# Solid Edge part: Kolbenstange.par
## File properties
Username: bmolnar
Dokumentum tartalom típus: 0
Author: bmolnar
Last saved by: bmolnar
Revision: 81
Sűrűség: 0,000 kg/m^3
Pontosság: 0,990
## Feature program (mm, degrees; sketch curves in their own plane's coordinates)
base feature "unnamed BaseFeature 1"
sketch for "unnamed Protrusion 1" plane through (34.5, 0, 0) normal (1, 0, 0) x-axis (0, 0, -1)
  circle centre (0, 0) radius 50
extrude "unnamed Protrusion 1" add finite 28 along +normal
sketch for "Furat_1" plane through (-15, 0, 0) normal (-1, 0, 0) x-axis (0, -1, 0)
hole "Furat_1" diameter 10 finite  VBottomAngle = 118 deg
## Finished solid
Body 1: solid body, 13 faces, 19 edges, 8 vertices.
  Faces by surface: plane 7, cylinder 3, cone 2, torus 1
  Edges by curve: circle 9, line 6, ellipse 2, intersection 2
Bounding box of the edges (mm; curved faces can reach further): 77.545 x 100.000 x 100.000, from (-15.0451, -50, -50) to (62.5, 50, 50).
Cylindrical faces by radius (mm): R5 x1, R12.5 x1, R50 x1
Conical faces (half-angle, radius in mm at the cone's reference point): 45 deg R5.553 x1, 59 deg R5 x1
Toroidal faces (ring radius, tube radius in mm): R10.7 r1.8 x1
Planar faces by outward normal: +x 1, +y 1, -x 2, -y 1, oblique 2
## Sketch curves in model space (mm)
circle centre (34.5, 0, 0) radius 50
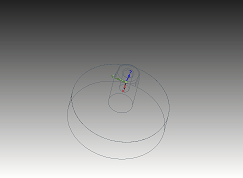
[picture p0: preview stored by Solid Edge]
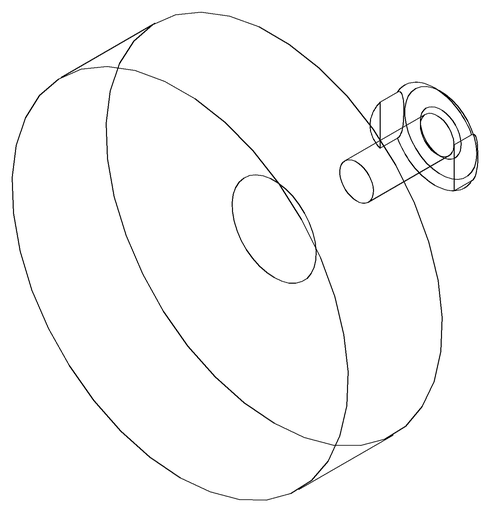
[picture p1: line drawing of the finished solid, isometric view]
